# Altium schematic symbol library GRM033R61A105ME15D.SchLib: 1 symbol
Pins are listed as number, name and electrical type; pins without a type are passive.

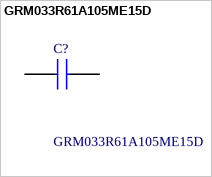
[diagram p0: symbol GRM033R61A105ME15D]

## GRM033R61A105ME15D
designator C?
Multilayer Ceramic Capacitors MLCC - SMD/SMT 0201 1.0uF 10volts; Manufacturer_Name: Murata Electronics; Geometry.Height: 0.33mm
footprint CAPC0603X33N
pins: 1, 2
